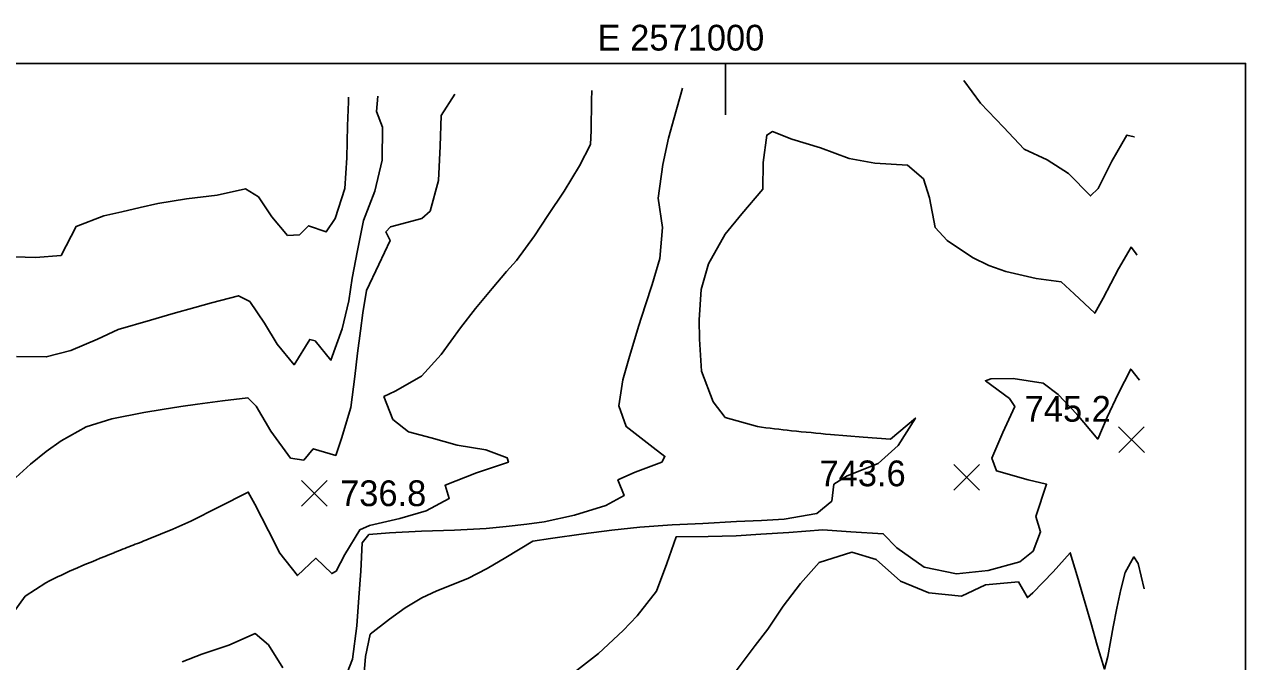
# Model space of a CAD drawing. Extents: x 2566079 to 2571326, y 424054 to 426896.
# Drawn here: x 2570592 to 2571303, y 426525 to 426896 of the extents above; entities that cross this region are included whole.
import ezdxf

# ---------------------------------------------------------------- set-up
doc = ezdxf.new("R2010")
doc.units = 0
for name, color, linetype in [('Contour_ADS_Major', 7, 'Continuous'), ('Contour_ADS_Minor', 7, 'Continuous'), ('Contour_ADS_Spot_Elevation', 7, 'Continuous'), ('Contour_ADS_State_Plane_Border', 7, 'Continuous')]:
    doc.layers.add(name, color=color, linetype=linetype)

# ---------------------------------------------------------------- blocks, each defined once
blk = doc.blocks.new('S750')
at = {"layer": 'Contour_ADS_Spot_Elevation'}
for p, q in [((-0.5, 0.498), (0.5, -0.498)), ((-0.498, -0.5), (0.498, 0.5))]:
    blk.add_line(p, q, dxfattribs=at)

msp = doc.modelspace()

# ---------------------------------------------------------------- linework, layer by layer
at = {"layer": 'Contour_ADS_Major'}
for points in [[(2570975.04, 426859.4), (2570970.15, 426842.13), (2570966.77, 426830.12), (2570963.45, 426814.85), (2570960.9, 426795.34), (2570963.31, 426778.07), (2570961.8, 426760.04), (2570957.22, 426745.04), (2570953.43, 426733.2), (2570949.41, 426720.51), (2570943.66, 426701.57), (2570940.28, 426689.35), (2570937.82, 426674.25), (2570942.14, 426662.22), (2570957.82, 426650.04), (2570964.76, 426644.84), (2570962.9, 426641.49), (2570947.32, 426635.54), (2570937.4, 426631.13), (2570940.91, 426621.99), (2570930.28, 426616.26), (2570912.1, 426610.66), (2570894.39, 426606.71), (2570884.36, 426605.34), (2570872.37, 426603.9), (2570860.64, 426602.74), (2570842.11, 426601.83), (2570823.01, 426601.19), (2570804.28, 426600.2), (2570792.32, 426599.35), (2570788.49, 426594.53), (2570787.61, 426578.04), (2570786.41, 426562.61), (2570785.23, 426546.06), (2570782.76, 426526.65), (2570776.66, 426510.83)], [(2571238.08, 426830.86), (2571238, 426831), (2571233.81, 426832.03), (2571224.99, 426816.77), (2571217.09, 426800.95), (2571212.54, 426796.59), (2571199.89, 426809.7), (2571187.42, 426817.54), (2571173.99, 426823.84), (2571162.01, 426836.66), (2571148.51, 426850.57), (2571138.82, 426863.81)], [(2570742.29, 426521.75), (2570733.83, 426535.09), (2570726.14, 426541.65), (2570710.81, 426534.93), (2570695.09, 426529.67), (2570683.51, 426525.15)]]:
    msp.add_lwpolyline(points, dxfattribs=at)
at = {"layer": 'Contour_ADS_Minor'}
for points in [[(2570780.48, 426854.17), (2570780.38, 426851.3), (2570779.9, 426837.39), (2570779.42, 426818.72), (2570778.35, 426800.91), (2570772.67, 426783.42), (2570767.53, 426775.59), (2570757.18, 426779.14), (2570751.98, 426773.98), (2570744.94, 426773.59), (2570735.77, 426784.36), (2570728.02, 426795.99), (2570720.41, 426800.62), (2570704.04, 426797.08), (2570686.02, 426794.85), (2570669.4, 426792.1), (2570659.08, 426789.79), (2570648.35, 426787.36), (2570637.98, 426785.03), (2570621.88, 426778.83), (2570613.03, 426761.83), (2570598.23, 426760.6), (2570580.19, 426761.28)], [(2570842.36, 426855.83), (2570834.36, 426843.44), (2570833.88, 426825.5), (2570832.95, 426805.6), (2570827.98, 426787.72), (2570823.17, 426783.44), (2570804.98, 426778.51), (2570802.2, 426775.67), (2570804.68, 426770.67), (2570798.15, 426756.53), (2570790.96, 426741.38), (2570788.87, 426728.48), (2570787.41, 426718.06), (2570785.73, 426704.96), (2570784.06, 426691.43), (2570781.89, 426673.35), (2570776.44, 426655.17), (2570773, 426645.38), (2570759.95, 426649.28), (2570754.34, 426642.68), (2570746.69, 426643.88), (2570735.28, 426659.61), (2570726.59, 426674.14), (2570721.9, 426678.99), (2570707.11, 426677.21), (2570692.54, 426675.18), (2570682.74, 426673.81), (2570672.01, 426672.21), (2570661.32, 426670.48), (2570642.63, 426666.69), (2570627.68, 426661.96), (2570613.15, 426653.92), (2570604.39, 426647.63), (2570595.24, 426640.25), (2570586.75, 426632.55)], [(2570797.63, 426854.63), (2570796.72, 426845.83), (2570800.32, 426836.56), (2570800.11, 426817.44), (2570795.8, 426799.36), (2570789.15, 426782.31), (2570785.78, 426764.84), (2570782.66, 426748.72), (2570780.68, 426735.39), (2570776.69, 426719.08), (2570770.2, 426700.84), (2570761.02, 426712.12), (2570757.85, 426712.96), (2570748.74, 426698.24), (2570738.93, 426710.11), (2570731.46, 426722.51), (2570722.91, 426735.08), (2570716.32, 426738.44), (2570700.7, 426734.31), (2570690.98, 426731.53), (2570678.35, 426727.97), (2570665.2, 426724.26), (2570646.23, 426718.83), (2570634.19, 426713.05), (2570618.78, 426706.42), (2570604.42, 426702.74), (2570587.09, 426702.97)], [(2570922.13, 426857.98), (2570921.98, 426852.11), (2570921.78, 426834.59), (2570921.49, 426826.6), (2570914.97, 426814.04), (2570906.12, 426799.24), (2570896.49, 426785.14), (2570888.86, 426773.28), (2570878.23, 426758.99), (2570872.55, 426752.44), (2570864.15, 426742.57), (2570854.51, 426730.93), (2570845.64, 426719.77), (2570834.4, 426704.12), (2570823.06, 426691.52), (2570807.6, 426682.88), (2570801.1, 426679.64), (2570806.35, 426666.41), (2570815.46, 426659.1), (2570828.66, 426655.73), (2570843.81, 426651.29), (2570860.52, 426648.73), (2570872.8, 426644), (2570873.63, 426641.48), (2570855.08, 426635.19), (2570836.69, 426628.01), (2570839.09, 426620.27), (2570825.78, 426613.19), (2570810.34, 426608.71), (2570792.61, 426604.58), (2570786.98, 426602.08), (2570778.38, 426587.67), (2570773.29, 426577.97), (2570770.69, 426576.53), (2570761.45, 426585.47), (2570750.77, 426575.35), (2570740.53, 426588.51), (2570733.95, 426601.54), (2570725.96, 426616.99), (2570722.08, 426624.05), (2570704.77, 426615.29), (2570688.54, 426607.04), (2570678.21, 426602.45), (2570663.68, 426596.52)], [(2571239.61, 426762.14), (2571239.32, 426762.62), (2571236.21, 426766.72), (2571228.85, 426754.07), (2571219.99, 426736.9), (2571215.11, 426728.18), (2571203.1, 426739.58), (2571195.59, 426746.49), (2571181.04, 426748.53), (2571163.33, 426752.56), (2571153.37, 426756.08), (2571143.93, 426760.66), (2571129.15, 426770.57), (2571122.19, 426778.22), (2571118.93, 426795.38), (2571115.33, 426806.44), (2571106.09, 426814.41), (2571086.95, 426815.73), (2571072.09, 426818.4), (2571055.35, 426824.64), (2571038.66, 426829.54), (2571027.33, 426834.06), (2571024.02, 426831.99), (2571021.89, 426816.12), (2571021.7, 426800.48), (2571009.53, 426786.06), (2570999.85, 426774.34), (2570990.2, 426756.9), (2570985.89, 426741.98), (2570984.77, 426724.47), (2570984.82, 426713.06), (2570986.09, 426694.52), (2570992.79, 426676.56), (2570999.84, 426667.45), (2571018.59, 426662.23)], [(2571241.23, 426689.2), (2571236.01, 426695.72), (2571228.63, 426681.27), (2571222.4, 426667.63), (2571216.84, 426654.91), (2571204.6, 426669.52), (2571193.73, 426680.81), (2571185.13, 426687.47), (2571167.54, 426690.28), (2571154.49, 426690.03), (2571151.4, 426688.86), (2571165.45, 426678.51), (2571168.49, 426673.9), (2571161.48, 426658.7), (2571155.18, 426643.71), (2571157.83, 426636.5), (2571176.38, 426631.16), (2571186.99, 426628.56), (2571180.86, 426609.75), (2571183.57, 426600.95), (2571179.17, 426589.71), (2571171.46, 426583.38), (2571152.92, 426578.28), (2571134.57, 426576.46), (2571115.77, 426580.35), (2571099.82, 426591.47), (2571091.94, 426599.76), (2571073.01, 426600.8), (2571056.67, 426602.12), (2571036.87, 426600.58), (2571020.62, 426599.61), (2571006.2, 426598.63), (2570989.89, 426598.13), (2570971.3, 426597.99), (2570965.88, 426582.46), (2570959.88, 426566.26), (2570948.65, 426551.96), (2570940.36, 426543.46), (2570926, 426530.03), (2570912.13, 426519.08)], [(2571061.17, 426657.62), (2571080.24, 426656.01), (2571096.04, 426654.78), (2571110.62, 426667.11), (2571100.66, 426651.15), (2571088.93, 426640.67), (2571070.86, 426633.44), (2571063.05, 426628.55), (2571061.97, 426618.81), (2571053.16, 426611.65), (2571034.1, 426608.35), (2571020.95, 426607.57), (2571006.48, 426606.82), (2570986.88, 426605.81), (2570968.97, 426605.03), (2570950.17, 426603.66), (2570933.91, 426601.91), (2570917.39, 426599.65), (2570898.12, 426596.99), (2570887.74, 426595.48), (2570872.18, 426585.95), (2570861.13, 426579.45), (2570850.01, 426573.62), (2570831.89, 426566.49), (2570823.14, 426562.49), (2570813.53, 426556.6), (2570804.26, 426550.02), (2570793, 426541.17), (2570790.31, 426528.19), (2570789.62, 426518.74)], [(2571243.94, 426567.77), (2571240.33, 426582.35), (2571237.85, 426586.28), (2571232.77, 426577.19), (2571230.27, 426567.34), (2571227.89, 426556.4), (2571225.74, 426545.57), (2571222.61, 426528.34), (2571220.86, 426520.88), (2571216.55, 426534.81), (2571212.82, 426548.03), (2571208.53, 426562.72), (2571204.83, 426575.25), (2571200.78, 426588.65), (2571190.85, 426577.64), (2571179.08, 426565.25), (2571175.82, 426562.57), (2571170.61, 426571.72), (2571151.39, 426569.92), (2571137.42, 426563.41), (2571118.51, 426565.35), (2571101.99, 426572.2), (2571087.71, 426584.84), (2571073.55, 426589.12), (2571054.52, 426583.03), (2571043.63, 426570.7), (2571033.52, 426557.5), (2571024.7, 426544.13), (2571017.39, 426534.66), (2571006.21, 426519.91)], [(2570604.12, 426571.18), (2570592.2, 426563.46), (2570580.71, 426547.41)]]:
    msp.add_lwpolyline(points, dxfattribs=at)
for centre, radius, start, end in [((2571084.31, 427114.52), 457.04, 261.73304, 264.25051), ((2571176.84, 427990.4), 1337.79, 264.06526, 265.03974), ((2570105.57, 427996.73), 1507.34, 291.32894, 291.73184), ((2570987.4, 425725.06), 929.46, 111.68555, 113.11242), ((2571177.7, 425248.93), 1442.22, 111.29984, 111.7213), ((2570731.04, 426327.35), 274.89, 113.24533, 117.49779)]:
    msp.add_arc(centre, radius, start, end, dxfattribs=at)
at = {"layer": 'Contour_ADS_State_Plane_Border'}
msp.add_line((2571000, 426843.74), (2571000, 426873.74), dxfattribs=at)
msp.add_lwpolyline([(2566079.33, 424077.11), (2571302.93, 424077.11), (2571302.93, 426873.74), (2566079.33, 426873.74), (2566079.33, 424077.11)], close=True, dxfattribs=at)

# ---------------------------------------------------------------- block references
at = {"layer": 'Contour_ADS_Spot_Elevation', "xscale": 15, "yscale": 15}
for p in [(2571236.49, 426654.64), (2571140.52, 426632.69), (2570760.55, 426623.35)]:
    msp.add_blockref('S750', p, dxfattribs=at)

# ---------------------------------------------------------------- texts
at = {"layer": 'Contour_ADS_Spot_Elevation'}
for s, p in [('745.2', (2571174.27, 426665.04)), ('743.6', (2571054.79, 426627.43)), ('736.8', (2570775.55, 426615.85))]:
    msp.add_text(s, height=15, dxfattribs=at).set_placement(p)
at = {"layer": 'Contour_ADS_State_Plane_Border'}
msp.add_text(' E 2571000', height=15, dxfattribs=at).set_placement((2570920, 426881.24))

doc.saveas('drawing.dxf')
